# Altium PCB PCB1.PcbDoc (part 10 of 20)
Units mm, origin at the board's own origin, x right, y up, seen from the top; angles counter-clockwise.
Board outline 294.51 x 138.18 mm, 12 copper layers (Top Layer 1 _Signal, L2_GND, L3_Signals, L4_GND, L5_POWER, L6_Signals, L7_GND, L8_Signals, L9_GND, L10_POWER, L11_GND, Bottom Layer_Signals), stack 1.788 mm thick; 1254 components, 836 nets, 5699 pads, 2073 vias.
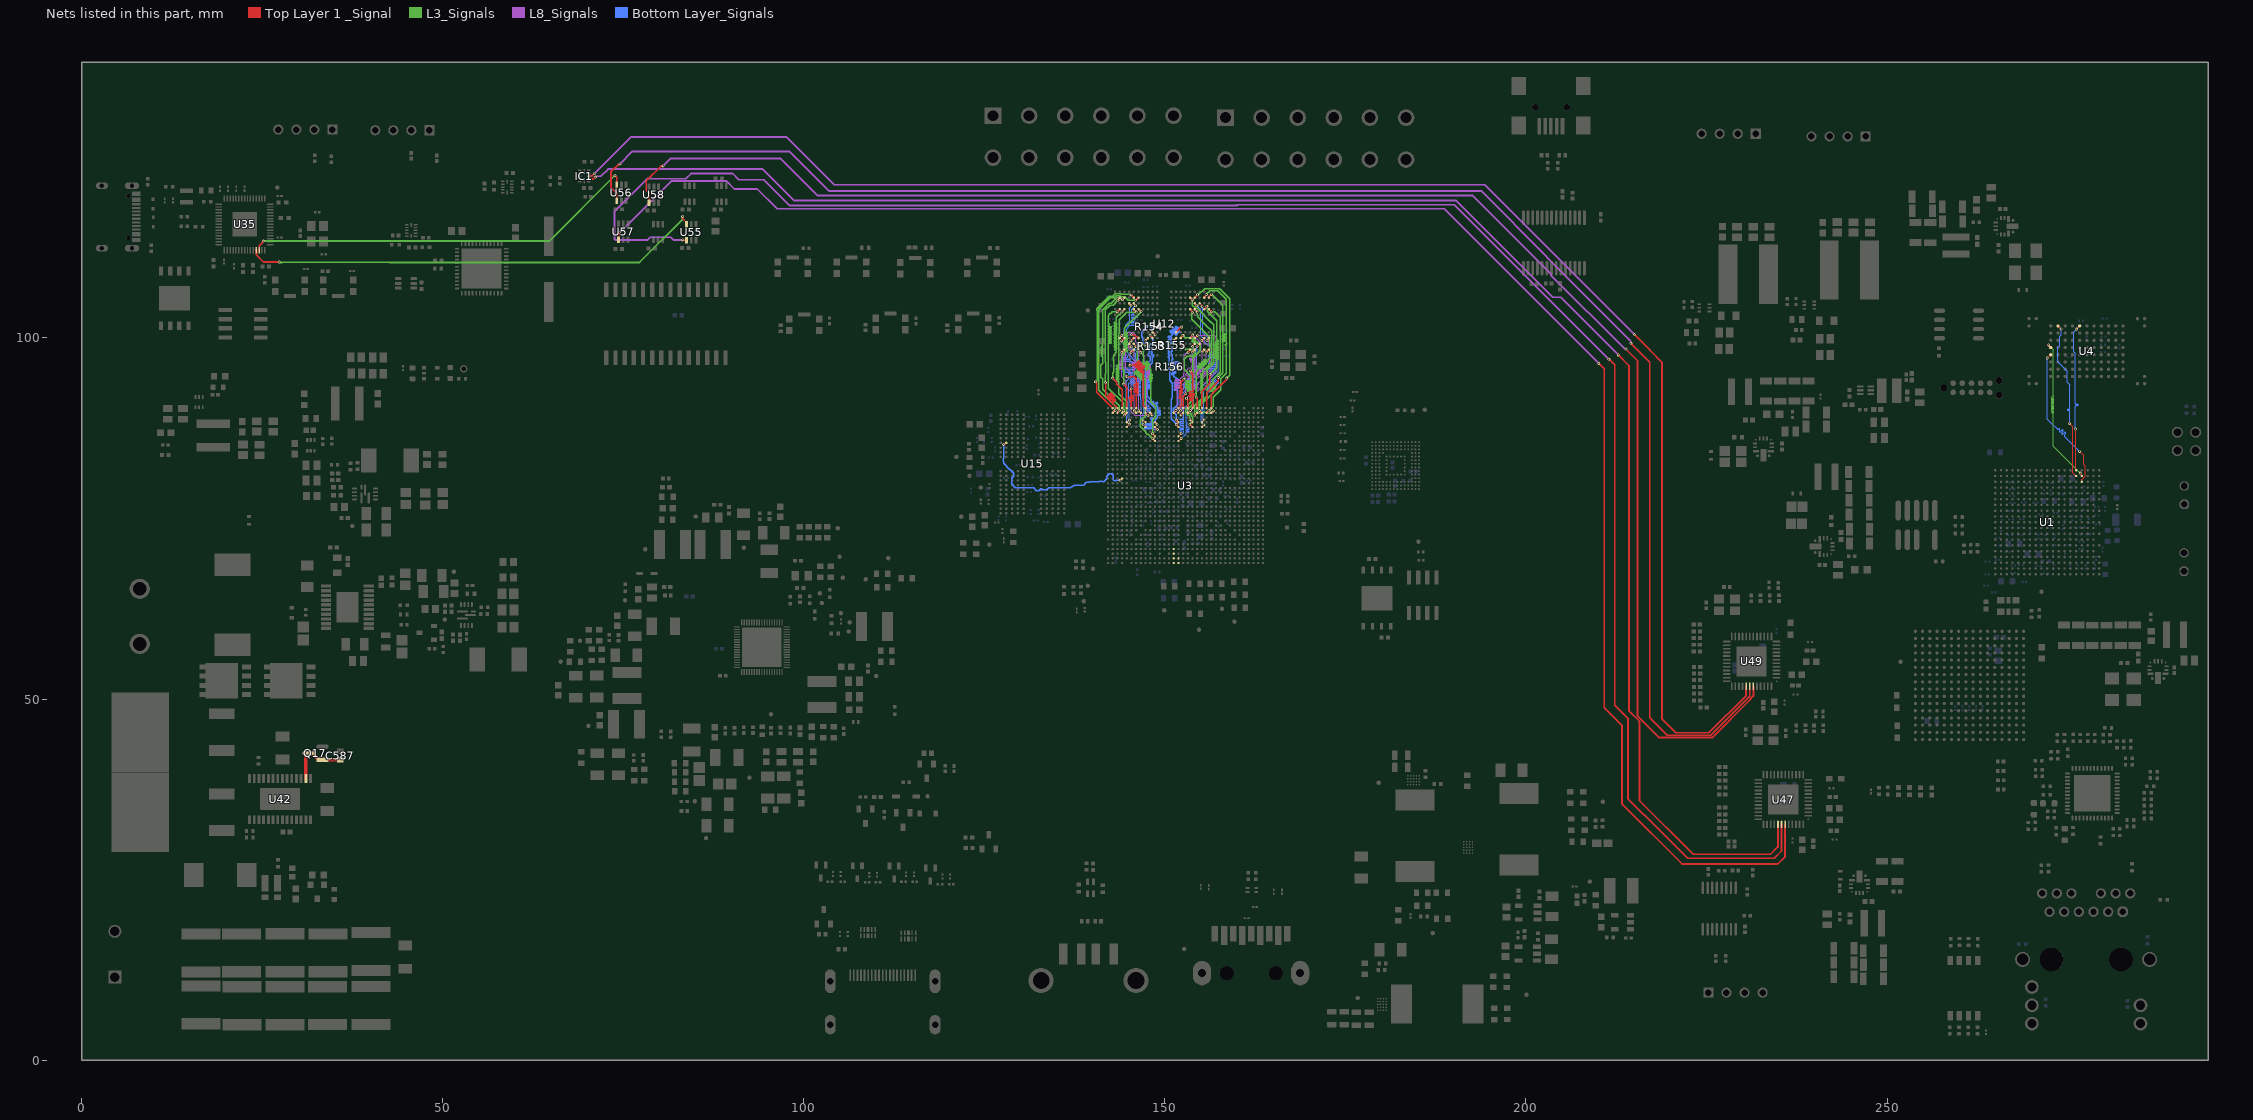
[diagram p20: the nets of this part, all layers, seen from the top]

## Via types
v1: diameter 0.4, hole 0.2, Top Layer 1 _Signal to Bottom Layer_Signals, 2009 vias
v2: diameter 0.508, hole 0.254, Top Layer 1 _Signal to Bottom Layer_Signals, 36 vias
v3: diameter 0.5, hole 0.2, Top Layer 1 _Signal to Bottom Layer_Signals, 12 vias
v4: diameter 1.27, hole 0.711, Top Layer 1 _Signal to Bottom Layer_Signals, 6 vias
v5: diameter 0.3, hole 0.2, Top Layer 1 _Signal to Bottom Layer_Signals, 5 vias
v6: diameter 0.254, hole 0.2, Top Layer 1 _Signal to Bottom Layer_Signals, 3 vias
v7: diameter 0.305, hole 0.2, Top Layer 1 _Signal to Bottom Layer_Signals, 1 vias
v8: diameter 0.254, hole 0.152, Top Layer 1 _Signal to Bottom Layer_Signals, 1 vias

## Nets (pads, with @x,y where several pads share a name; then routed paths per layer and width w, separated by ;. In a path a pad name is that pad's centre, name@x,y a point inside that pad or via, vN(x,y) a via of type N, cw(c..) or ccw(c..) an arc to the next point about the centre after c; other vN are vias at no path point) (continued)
DDR_CH1_DQ0_D: U3.A17 U12.AA2 | length 13.8
  Top Layer 1 _Signal w0.203: U3.A17@152.529,90.278 152.529,91.909 v1(152.889,92.269) ; v1@155.749,98.045 v1(155.758,98.045) 155.763,98.05 155.766,98.05 U12.AA2@156.104,98.389
  L8_Signals w0.135: v1(152.889,92.269) 152.889,93.591 153.838,94.539 153.885,94.587 153.838,94.634 153.951,94.747 154.197,94.502 154.311,94.615 154.065,94.861 154.178,94.974 154.424,94.728 154.537,94.842 154.291,95.087 154.405,95.201 154.651,94.955 154.764,95.068 154.518,95.314 154.631,95.427 154.877,95.182 154.991,95.295 154.745,95.541 154.858,95.654 155.104,95.408 155.217,95.522 154.971,95.767 155.085,95.881 155.331,95.635 155.444,95.748 155.245,95.947 155.372,96.074 155.758,96.46 v1(155.758,98.045)
DDR_CH1_DQ1_C: U3.B9 U12.C2 | length 15.5
  Top Layer 1 _Signal w0.203: v1(144.028,97.964) 144.028,97.988 144.404,98.365 U12.C2@144.404,98.389 ; U3.B9@147.329,89.628 147.329,89.602 147.651,89.28 v1(147.654,89.28) v1@147.639,89.265
  L8_Signals w0.135: v1(144.028,97.964) 144.028,97.3 144.028,97.155 143.96,97.155 143.96,96.995 144.081,96.995 144.081,96.835 143.708,96.835 143.708,96.674 144.081,96.674 144.081,96.514 143.708,96.514 143.708,96.354 144.081,96.354 144.081,96.194 143.708,96.194 143.708,96.033 144.081,96.033 144.081,95.873 143.708,95.873 143.708,95.713 144.028,95.713 144.028,95.645 144.028,94.631 144.642,94.017 144.642,93.176 145.338,92.48 145.338,89.791 145.849,89.28 v1(147.654,89.28)
DDR_CH1_DQ1_D: U3.B16 U12.Y2 | length 16.5
  Top Layer 1 _Signal w0.205: U3.B16@151.879,89.628 151.879,89.659 152.159,89.938 v1(152.165,89.938) ; v1(155.143,98.027) 155.143,98.038 155.454,98.35 U12.Y2@155.454,98.389
  L8_Signals w0.135: v1(152.165,89.938) 152.165,92.632 152.638,93.104 152.638,93.743 153.12,94.225 153.168,94.273 153.033,94.407 153.147,94.521 153.328,94.339 153.441,94.452 153.063,94.831 153.176,94.944 153.521,94.6 153.634,94.713 153.383,94.964 153.497,95.077 153.734,94.84 153.848,94.953 153.712,95.088 153.826,95.201 153.961,95.066 154.074,95.18 153.907,95.347 154.02,95.46 154.188,95.293 154.301,95.406 154.072,95.635 154.185,95.749 154.414,95.52 154.528,95.633 154.299,95.862 154.412,95.975 154.641,95.746 154.754,95.86 154.525,96.089 154.639,96.202 154.867,95.973 154.981,96.086 154.591,96.476 154.704,96.589 155.141,96.152 155.255,96.266 155.143,96.377 155.143,96.74 v1(155.143,98.027)
DDR_CH1_DQ2_C: U3.A9 U12.E2 | length 15.7
  Top Layer 1 _Signal w0.203: v1(145.177,96.215) 145.197,96.195 145.643,96.195 145.784,96.195 145.785,96.193 146.4,96.808 146.562,96.647 145.929,96.014 146.09,95.852 146.723,96.485 146.885,96.324 146.252,95.691 146.414,95.529 147.047,96.162 147.208,96 146.575,95.367 146.737,95.206 147.014,95.483 147.176,95.321 146.917,95.062 147.005,94.973 147.022,94.957 147.022,90.617 147.329,90.31 U3.A9@147.329,90.278 ; v1(145.338,97.968) 145.338,98.023 U12.E2@145.704,98.389
  L8_Signals w0.135: v1(145.177,96.215) 145.177,97.735 145.338,97.896 v1(145.338,97.968)
DDR_CH1_DQ2_D: U3.A16 U12.V2 | length 16
  Top Layer 1 _Signal w0.205: U3.A16@151.879,90.278 152.241,90.64 152.241,91.519 152.241,91.622 152.001,91.622 152.001,91.853 152.241,91.853 152.241,92.083 152.074,92.083 152.074,92.314 152.413,92.314 152.413,92.544 152.062,92.544 152.062,92.775 152.413,92.775 152.413,93.006 152.163,93.006 152.163,93.236 152.241,93.236 152.241,93.612 152.241,93.914 v1(152.629,94.302) ; v1(153.811,98.04) 153.811,98.046 U12.V2@154.154,98.389
  L8_Signals w0.135: v1(152.629,94.302) 152.844,94.517 152.844,94.928 153.071,95.154 153.071,95.627 153.298,95.853 153.671,95.853 153.706,95.888 153.774,95.956 153.774,96.09 153.74,96.09 153.74,96.251 154.069,96.251 154.069,96.411 153.768,96.411 153.768,96.571 154.154,96.571 154.154,96.732 153.607,96.732 153.607,96.892 154.154,96.892 154.154,97.052 153.428,97.052 153.428,97.212 154.154,97.212 154.154,97.373 153.428,97.373 153.428,97.533 153.811,97.533 153.811,97.651 v1(153.811,98.04)
DDR_CH1_DQ3_C: U3.B10 U12.F2 | length 16.5
  Top Layer 1 _Signal w0.203: U12.F2@146.354,98.389 146.354,98.349 146.658,98.045 v1(146.658,97.96) ; U3.B10@147.979,89.628 147.979,89.596 v1(148.237,89.339) v1@148.237,89.269
  L8_Signals w0.135: v1(146.658,97.96) 147.113,97.506 147.113,96.579 147.517,96.175 147.517,96.108 148.065,96.108 148.065,95.948 147.492,95.948 147.492,95.787 148.065,95.787 148.065,95.627 147.492,95.627 147.492,95.467 148.065,95.467 148.065,95.306 147.492,95.306 147.492,95.146 148.065,95.146 148.065,94.986 147.492,94.986 147.492,94.826 148.065,94.826 148.065,94.665 147.492,94.665 147.492,94.505 147.765,94.505 147.765,94.345 147.517,94.345 147.517,92.97 147.517,90.059 v1(148.237,89.339)
DDR_CH1_DQ3_D: U3.B15 U12.U2 | length 16.6
  Top Layer 1 _Signal w0.205: U3.B15@151.229,89.628 151.229,89.639 151.53,89.94 v1(151.53,89.952) ; v1(153.209,97.997) 153.246,98.035 153.246,98.092 153.504,98.35 U12.U2@153.504,98.389
  L8_Signals w0.135: v1(151.53,89.952) 151.53,90.026 151.681,90.177 151.681,92.062 151.749,92.13 151.749,92.421 151.681,92.489 151.681,92.772 151.681,92.84 151.43,92.84 151.43,93 152.178,93 152.178,93.16 151.43,93.16 151.43,93.321 152.178,93.321 152.178,93.481 151.43,93.481 151.43,93.641 152.178,93.641 152.178,93.801 151.43,93.801 151.43,93.962 152.178,93.962 152.178,94.122 151.43,94.122 151.43,94.282 152.111,94.282 152.226,94.397 152.625,94.797 152.625,95.018 152.708,95.101 152.708,96.375 152.701,96.382 152.701,96.748 152.681,96.767 152.681,97.058 152.701,97.078 152.701,97.657 152.907,97.862 153.002,97.862 153.137,97.997 v1(153.209,97.997)
DDR_CH1_DQ4_C: U3.A6 U12.F4 | length 14.2
  Top Layer 1 _Signal w0.203: v1(145.352,92.964) 145.366,92.95 145.366,92.108 145.366,92.007 145.622,92.007 145.622,91.778 145.062,91.778 145.062,91.549 145.622,91.549 145.622,91.321 145.238,91.321 145.238,91.092 145.366,91.092 145.366,90.619 145.366,90.292 U3.A6@145.379,90.278 ; v1(145.393,100.452) 145.431,100.414 145.713,100.414 145.778,100.349 145.854,100.349 146.062,100.141 146.162,100.141 146.315,99.989 U12.F4@146.354,99.989
  L8_Signals w0.135: v1(145.352,92.964) 145.357,92.969 145.357,95.095 144.593,95.859 144.593,97.724 144.598,97.728 144.598,98.2 144.593,98.205 144.593,100.12 144.934,100.461 145.384,100.461 v1(145.393,100.452)
DDR_CH1_DQ4_D: U3.A19 U12.U4 | length 15.5
  Top Layer 1 _Signal w0.203: U12.U4@153.504,99.989 153.863,100.347 v1(153.863,100.401) ; v1(153.556,95.428) 153.556,95.375 153.881,95.05 153.881,93.532 153.881,92.742 153.948,92.742 153.948,92.513 153.348,92.513 153.348,92.285 154.063,92.285 154.063,92.056 153.348,92.056 153.348,91.827 153.959,91.827 153.959,91.599 153.467,91.599 153.467,91.37 153.8,91.37 153.8,91.269 153.8,91.228 153.829,91.199 U3.A19@153.829,90.278
  L8_Signals w0.135: v1(153.556,95.428) 154.372,96.245 154.372,97.754 155.041,98.423 155.041,99.174 154.754,99.461 154.754,99.51 v1(153.863,100.401)
DDR_CH1_DQ5_C: U3.B7 U12.E4 | length 15
  Top Layer 1 _Signal w0.205: v1(145.297,99.599) 145.306,99.599 145.695,99.989 U12.E4@145.704,99.989 ; v1(145.768,89.859) 145.998,89.628 U3.B7@146.029,89.628
  L8_Signals w0.135: v1(145.297,99.599) 144.977,99.28 144.977,98.631 145.275,98.333 145.47,98.333 145.768,98.035 145.768,97.822 145.768,97.037 ; 145.767,97.037 145.767,96.876 145.994,96.876 145.994,96.716 145.526,96.716 145.526,96.556 145.994,96.556 145.994,96.396 145.528,96.396 145.528,96.235 145.994,96.235 145.994,96.075 145.526,96.075 145.526,95.915 145.994,95.915 145.994,95.755 145.526,95.755 145.526,95.594 145.768,95.594 145.768,95.527 v1(145.768,89.859)
DDR_CH1_DQ5_D: U3.B18 U12.V4 | length 15.3
  Top Layer 1 _Signal w0.203: U3.B18@153.179,89.628 153.211,89.628 153.527,89.944 v1(153.527,89.953) ; U12.V4@154.154,99.989 154.506,100.34 154.514,100.34 v1(154.531,100.358)
  L8_Signals w0.135: v1(153.527,89.953) 153.527,90.025 153.64,90.138 ; 153.64,90.139 153.984,90.482 153.984,92.155 156.595,94.766 156.595,94.806 157.124,95.336 157.124,100.072 156.838,100.358 v1(154.531,100.358)
DDR_CH1_DQ6_C: U3.A7 U12.C4 | length 15
  Top Layer 1 _Signal w0.203: v1(143.979,99.589) 144.023,99.633 144.048,99.633 U12.C4@144.404,99.989 ; v1(144.764,94.628) 145.783,94.628 146.029,94.382 146.029,93.917 146.029,93.816 146.266,93.816 146.266,93.587 145.77,93.587 145.77,93.359 146.266,93.359 146.266,93.13 145.77,93.13 145.77,92.901 146.266,92.901 146.266,92.673 145.77,92.673 145.77,92.444 146.266,92.444 146.266,92.216 145.945,92.216 145.945,91.987 146.029,91.987 146.029,91.761 U3.A7@146.029,90.278
  L8_Signals w0.135: v1(143.979,99.589) 144.374,99.194 144.374,98.115 144.379,98.11 144.379,97.819 144.374,97.814 144.374,95.018 v1(144.764,94.628)
DDR_CH1_DQ6_D: U3.A18 U12.Y4 | length 14.8
  Top Layer 1 _Signal w0.205: v1(152.993,91.648) 152.993,91.596 153.179,91.409 U3.A18@153.179,90.278 ; v1(155.105,99.633) 155.105,99.636 155.454,99.985 U12.Y4@155.454,99.989
  L8_Signals w0.135: v1(152.993,91.648) 152.993,91.653 153.465,92.125 153.465,93.353 154.722,94.611 154.77,94.658 154.752,94.676 154.865,94.79 155.097,94.558 155.21,94.672 154.979,94.903 155.092,95.016 155.323,94.785 155.437,94.898 155.205,95.13 155.319,95.243 155.55,95.012 155.663,95.125 155.432,95.356 155.545,95.47 155.77,95.245 155.884,95.358 155.659,95.583 155.772,95.696 155.862,95.606 155.975,95.72 155.903,95.792 156.034,95.922 156.226,96.114 156.226,98.827 155.831,99.222 155.603,99.222 155.384,99.441 155.368,99.441 155.177,99.633 v1(155.105,99.633)
DDR_CH1_DQ7_C: U3.B8 U12.B4 | length 15.4
  Top Layer 1 _Signal w0.203: U12.B4@143.754,99.989 143.754,100.028 144.035,100.309 v1(144.035,100.348) ; v1@146.368,89.899 v1(146.381,89.899) 146.381,89.895 146.648,89.628 U3.B8@146.679,89.628
  L8_Signals w0.135: v1(144.035,100.348) 144.489,100.803 145.539,100.803 145.953,100.388 145.953,99.446 146.368,99.032 146.368,98.167 146.307,98.106 146.307,96.518 146.307,96.45 146.563,96.45 146.563,96.29 146.282,96.29 146.282,96.13 146.563,96.13 146.563,95.969 146.282,95.969 146.282,95.809 146.51,95.809 146.51,95.649 146.307,95.649 146.307,94.309 146.381,94.235 146.381,94.025 v1(146.381,89.899)
DDR_CH1_DQ7_D: U3.B17 U12.AA4 | length 16.2
  Top Layer 1 _Signal w0.203: v1(152.254,89.344) 152.254,89.348 152.529,89.624 U3.B17@152.529,89.628 ; v1(155.837,99.648) 155.837,99.682 156.104,99.949 U12.AA4@156.104,99.989
  L8_Signals w0.135: v1(152.254,89.344) 152.305,89.395 152.305,89.581 152.516,89.793 152.516,90.14 153.698,91.322 153.698,92.85 153.804,92.956 153.852,93.004 153.75,93.105 153.864,93.219 154.301,92.781 154.414,92.895 153.977,93.332 154.09,93.445 154.527,93.008 154.641,93.121 154.203,93.559 154.317,93.672 154.508,93.48 154.622,93.594 154.532,93.684 155.892,95.044 155.892,95.057 155.946,95.111 156.098,95.263 156.111,95.263 156.448,95.601 156.448,99.036 v1(155.837,99.648)
DDR_CH1_DQ8_C: U3.A3 U12.B11 | length 22
  Top Layer 1 _Signal w0.205: v1(141.768,93.82) 141.793,93.796 141.793,92.103 141.793,91.958 141.938,91.813 142.544,92.419 142.707,92.256 142.061,91.61 142.224,91.447 142.87,92.093 143.033,91.93 142.387,91.284 142.551,91.121 143.021,91.591 143.184,91.428 142.732,90.976 143.176,90.531 U3.A3@143.429,90.278 ; v1(143.504,105.223) 143.541,105.26 143.541,105.337 143.754,105.55 U12.B11@143.754,105.589
  L3_Signals w0.179: v1(141.768,93.82) 141.768,95.018 141.781,95.03 141.781,96.628 141.768,96.64 141.768,98.62 141.768,101.629 141.768,103.9 142.42,104.552 142.833,104.552 v1(143.504,105.223)
DDR_CH1_DQ8_D: U3.A22 U12.AA11 | length 19.8
  Top Layer 1 _Signal w0.203: U3.A22@155.779,90.278 155.779,92.388 157.407,94.015 157.407,94.506 v1(157.42,94.52) ; U12.AA11@156.104,105.589 156.104,105.629 156.172,105.696 156.172,105.741 v1(156.461,106.03)
  L3_Signals w0.179: v1(156.461,106.03) 157.994,104.497 157.994,100.686 157.994,100.596 158.259,100.596 158.259,100.392 157.917,100.392 157.917,100.187 158.259,100.187 158.259,99.982 157.917,99.982 157.917,99.778 158.259,99.778 158.259,99.573 157.974,99.573 157.974,99.368 157.994,99.368 157.994,98.27 157.994,95.153 157.42,94.58 v1(157.42,94.52)
DDR_CH1_DQ9_C: U3.B3 U12.C11 | length 21.8
  Top Layer 1 _Signal w0.203: v1(144.154,105.28) 144.154,105.309 144.404,105.56 U12.C11@144.404,105.589
  Top Layer 1 _Signal w0.205: U3.B3@143.429,89.628 143.429,89.641 143.706,89.918 v1(143.706,89.93)
  L3_Signals w0.179: v1(143.706,89.93) 143.706,90.579 141.395,92.89 141.395,94.328 141.138,94.585 141.138,96.231 141.395,96.488 141.395,97.348 141.395,97.437 141.162,97.437 141.162,97.642 141.42,97.642 141.42,97.847 141.162,97.847 141.162,98.051 141.42,98.051 141.42,98.256 141.162,98.256 141.162,98.461 141.42,98.461 141.42,98.666 141.162,98.666 141.162,98.87 141.42,98.87 141.42,99.075 141.322,99.075 141.322,99.28 141.395,99.28 141.395,101.306 141.395,103.899 142.311,104.815 142.568,104.815 143.349,105.596 143.659,105.596 143.819,105.437 143.938,105.437 144.094,105.28 v1(144.154,105.28)
DDR_CH1_DQ9_D: U3.B22 U12.Y11 | length 21.3
  Top Layer 1 _Signal w0.203: U12.Y11@155.454,105.589 155.454,105.629 155.761,105.935 v1(155.761,106.016) ; U3.B22@155.779,89.628 v1(156.097,89.945)
  L3_Signals w0.179: v1(155.761,106.016) 156.308,106.564 157.346,106.564 158.522,105.388 158.522,99.424 158.522,99.335 158.547,99.335 158.547,99.13 158.365,99.13 158.365,98.925 158.522,98.925 158.522,96.478 158.522,95.093 157.744,94.316 157.744,92.816 156.709,91.78 156.709,90.557 v1(156.097,89.945)
DDR_CH1_DQ10_C: U3.A2 U12.E11 | length 21.1
  Top Layer 1 _Signal w0.205: v1(140.405,93.926) 140.405,93.873 140.552,93.727 140.552,92.506 U3.A2@142.779,90.278 ; v1(145.325,105.96) 145.329,105.96 145.7,105.589 U12.E11@145.704,105.589
  L3_Signals w0.179: v1(140.405,93.926) 140.405,93.935 140.612,94.141 140.612,103.782 140.58,103.814 140.58,104.068 142.315,105.803 142.812,105.803 143.131,106.123 143.877,106.123 143.98,106.019 145.109,106.019 145.127,106.002 145.282,106.002 v1(145.325,105.96)
DDR_CH1_DQ10_D: U3.A23 U12.V11 | length 22.1
  Top Layer 1 _Signal w0.203: U12.V11@154.154,105.589 154.521,105.955 v1(154.521,105.975) ; U3.A23@156.429,90.278 156.429,92.164 158.537,94.272 158.537,94.405 v1(158.575,94.443)
  L3_Signals w0.179: v1(154.521,105.975) 154.563,106.017 154.702,106.017 155.517,106.832 157.567,106.832 158.987,105.413 158.987,94.855 v1(158.575,94.443)
DDR_CH1_DQ11_C: U3.B2 U12.F11 | length 22.1
  Top Layer 1 _Signal w0.203: U3.B2@142.779,89.628 142.779,89.66 143.091,89.971 v1(143.1,89.971) v1@143.101,89.969 ; v1(145.973,105.217) 145.978,105.217 146.35,105.589 U12.F11@146.354,105.589
  L3_Signals w0.179: v1(143.1,89.971) 143.1,90.534 140.875,92.759 140.875,103.991 142.424,105.54 142.921,105.54 143.24,105.86 143.768,105.86 143.928,105.7 144.47,105.7 144.952,105.217 v1(145.973,105.217)
DDR_CH1_DQ11_D: U3.B23 U12.U11 | length 21.3
  Top Layer 1 _Signal w0.205: U12.U11@153.504,105.589 153.504,105.583 153.805,105.282 v1(153.805,105.276) ; U3.B23@156.429,89.628 156.46,89.628 156.725,89.892 v1(156.725,89.895)
  L3_Signals w0.179: v1(153.805,105.276) 153.805,104.559 154.286,104.078 154.484,104.078 155.435,103.127 155.435,103.089 156.386,102.138 156.421,102.138 156.759,101.8 156.759,99.401 156.737,99.379 156.737,96.501 155.87,95.634 155.87,92.009 154.419,90.558 154.419,89.73 154.573,89.575 155.097,89.575 155.242,89.72 155.702,89.72 155.85,89.571 156.385,89.571 156.709,89.895 v1(156.725,89.895)
DDR_CH1_DQ12_C: U3.A5 U12.F9 | length 21.8
  Top Layer 1 _Signal w0.203: v1(144.291,93.598) 144.729,93.16 U3.A5@144.729,90.278 ; U12.F9@146.354,103.989 v1(146.701,103.642)
  L3_Signals w0.179: v1(144.291,93.598) 144.291,95.512 144.1,95.703 144.1,97.508 144.402,97.81 144.435,97.844 144.435,97.9 144.401,97.9 144.401,98.105 144.816,98.105 144.816,98.31 144.233,98.31 144.233,98.514 144.816,98.514 144.816,98.719 144.353,98.719 144.353,98.924 144.816,98.924 144.816,99.128 144.252,99.128 144.252,99.333 144.816,99.333 144.816,99.538 144.353,99.538 144.353,99.743 144.816,99.743 144.816,99.947 144.367,99.947 144.367,100.152 144.816,100.152 144.816,100.357 144.408,100.357 144.408,100.561 144.779,100.561 144.779,100.766 144.435,100.766 144.435,100.975 144.435,101.377 v1(146.701,103.642)
DDR_CH1_DQ12_D: U3.A20 U12.U9 | length 20.3
  Top Layer 1 _Signal w0.203: U12.U9@153.504,103.989 153.504,103.949 153.782,103.672 153.782,103.573 v1(153.819,103.535) ; v1(154.345,91.792) 154.345,91.739 154.479,91.604 U3.A20@154.479,90.278
  L3_Signals w0.179: v1(153.819,103.535) 153.819,103.475 153.708,103.363 153.708,102.617 156.211,100.114 156.211,97.22 156.076,97.086 155.92,96.929 156.03,96.819 155.886,96.674 155.514,97.046 155.369,96.901 155.78,96.49 155.635,96.345 155.224,96.756 155.079,96.612 155.491,96.2 155.346,96.055 154.935,96.467 154.79,96.322 155.201,95.911 155.056,95.766 154.645,96.177 154.5,96.033 154.762,95.771 154.698,95.708 154.335,95.344 154.335,91.802 v1(154.345,91.792)
DDR_CH1_DQ13_C: U3.B5 U12.E9 | length 22
  Top Layer 1 _Signal w0.203: v1(144.418,89.316) U3.B5@144.729,89.628 ; U12.E9@145.704,103.989 145.704,103.949 146.032,103.621 v1(146.032,103.582)
  L3_Signals w0.179: 143.606,93.671 143.606,92.291 144.576,91.321 144.576,91.233 144.686,91.123 144.686,89.644 144.418,89.376 v1(144.418,89.316) ; 143.606,93.982 143.606,93.987 143.246,93.987 143.246,94.192 143.631,94.192 143.631,94.397 143.246,94.397 143.246,94.601 143.631,94.601 143.631,94.806 143.246,94.806 143.246,95.011 143.631,95.011 143.631,95.216 143.246,95.216 143.246,95.42 143.631,95.42 143.631,95.625 143.246,95.625 143.246,95.83 143.631,95.83 143.631,96.035 143.306,96.035 143.306,96.239 143.606,96.239 143.606,96.8 143.606,100.447 143.709,100.55 143.709,102.551 144.74,103.582 v1(146.032,103.582) ; 143.607,93.672 143.607,93.898 143.607,93.982
DDR_CH1_DQ13_D: U3.B20 U12.V9 | length 20.9
  Top Layer 1 _Signal w0.203: v1(154.145,89.301) 154.149,89.301 154.476,89.628 U3.B20@154.479,89.628 ; U12.V9@154.154,103.989 154.154,103.949 154.418,103.686 154.418,103.616 v1(154.455,103.578)
  L3_Signals w0.179: v1(154.145,89.301) 154.145,90.656 155.24,91.751 155.24,92.258 155.24,92.348 154.991,92.348 154.991,92.553 155.265,92.553 155.265,92.757 154.991,92.757 154.991,92.962 155.265,92.962 155.265,93.167 154.991,93.167 154.991,93.371 155.265,93.371 155.265,93.576 154.991,93.576 154.991,93.781 155.265,93.781 155.265,93.986 154.991,93.986 154.991,94.19 155.265,94.19 155.265,94.395 154.991,94.395 154.991,94.6 155.265,94.6 155.265,94.805 154.991,94.805 154.991,95.009 155.24,95.009 155.24,95.282 155.24,95.376 156.474,96.61 156.474,100.782 156.496,100.804 156.496,100.977 155.822,101.65 155.818,101.65 154.524,102.944 154.524,102.99 154.455,103.059 v1(154.455,103.578)
DDR_CH1_DQ14_C: U3.A4 U12.C9 | length 21.7
  Top Layer 1 _Signal w0.203: v1(142.755,94.446) 143.324,93.876 143.324,93.611 144.079,92.856 U3.A4@144.079,90.278 ; v1(144.038,103.589) 144.038,103.606 144.404,103.972 U12.C9@144.404,103.989
  L3_Signals w0.179: v1(142.755,94.446) 142.755,95.121 142.935,95.302 142.935,95.821 142.926,95.83 142.926,96.926 142.859,96.994 142.859,97.303 142.926,97.371 142.926,97.618 143.292,97.983 143.292,98.186 143.292,98.275 143.082,98.275 143.082,98.48 143.317,98.48 143.317,98.685 142.961,98.685 142.961,98.89 143.317,98.89 143.317,99.094 142.961,99.094 142.961,99.299 143.317,99.299 143.317,99.504 142.961,99.504 142.961,99.709 143.317,99.709 143.317,99.913 142.961,99.913 142.961,100.118 143.317,100.118 143.317,100.323 142.961,100.323 142.961,100.527 143.317,100.527 143.317,100.732 142.961,100.732 142.961,100.937 143.317,100.937 143.317,101.142 142.961,101.142 142.961,101.346 143.317,101.346 143.317,101.551 142.961,101.551 142.961,101.756 143.317,101.756 143.317,101.96 143.009,101.96 143.009,102.165 143.292,102.165 143.292,102.304 143.292,102.843 v1(144.038,103.589)
DDR_CH1_DQ14_D: U3.A21 U12.Y9 | length 21.3
  Top Layer 1 _Signal w0.203: U3.A21@155.129,90.278 155.129,92.578 156.243,93.692 v1(156.243,94.912) ; U12.Y9@155.454,103.989 155.809,104.344 v1(155.809,104.388)
  L3_Signals w0.179: v1(155.809,104.388) 155.852,104.345 155.852,104.209 155.888,104.172 155.888,103.664 156.537,103.015 156.565,103.015 157.214,102.367 157.214,99.746 157.214,99.656 157.391,99.656 157.391,99.452 157.022,99.452 157.022,99.247 157.391,99.247 157.391,99.042 157,99.042 157,98.837 157.391,98.837 157.391,98.633 157,98.633 157,98.428 157.391,98.428 157.391,98.223 157,98.223 157,98.019 157.391,98.019 157.391,97.814 157,97.814 157,97.609 157.391,97.609 157.391,97.404 157,97.404 157,97.2 157.391,97.2 157.391,96.995 157.118,96.995 157.118,96.79 157.214,96.79 157.214,95.882 157.202,95.87 v1(156.243,94.912)
DDR_CH1_DQ15_C: U3.B4 U12.B9 | length 21.5
  Top Layer 1 _Signal w0.205: v1(143.411,103.603) 143.411,103.624 143.754,103.968 U12.B9@143.754,103.989 ; U3.B4@144.079,89.628 144.079,89.659 144.312,89.892 v1(144.312,89.9)
  L3_Signals w0.179: v1(143.411,103.603) 142.746,103.603 142.579,103.437 142.44,103.437 142.221,103.218 142.221,103.079 142.181,103.039 142.181,102.498 142.181,101.932 142.265,101.932 142.265,101.728 142.156,101.728 142.156,101.523 142.56,101.523 142.56,101.318 142.156,101.318 142.156,101.114 142.56,101.114 142.56,100.909 142.156,100.909 142.156,100.704 142.56,100.704 142.56,100.499 142.156,100.499 142.156,100.295 142.56,100.295 142.56,100.09 142.156,100.09 142.156,99.885 142.56,99.885 142.56,99.681 142.156,99.681 142.156,99.476 142.56,99.476 142.56,99.271 142.156,99.271 142.156,99.066 142.181,99.066 142.181,98.977 142.181,93.064 144.312,90.933 v1(144.312,89.9)
DDR_CH1_DQ15_D: U3.B21 U12.AA9 | length 21.1
  Top Layer 1 _Signal w0.205: v1(154.792,89.949) 154.8,89.949 155.113,89.636 155.113,89.628 U3.B21@155.129,89.628 ; U12.AA9@156.104,103.989 156.104,103.982 156.466,103.621 v1(156.466,103.614)
  L3_Signals w0.179: v1(154.792,89.949) 154.792,90.511 156.61,92.329 156.61,92.379 156.61,92.469 156.61,92.648 156.196,92.648 156.196,92.853 157.033,92.853 157.033,93.058 156.196,93.058 156.196,93.262 157.033,93.262 157.033,93.467 156.196,93.467 156.196,93.672 156.794,93.672 156.794,93.877 156.612,93.877 156.612,94.054 156.612,94.151 156.613,94.24 157.654,95.282 157.654,102.872 156.912,103.614 v1(156.466,103.614)
DDR_CH1_DQS0_C_N: U3.D9 U12.E3 | length 20.1
  Top Layer 1 _Signal w0.161: U12.E3@145.704,99.189 146.017,98.876 v1(146.017,98.781) ; v1(146.999,88.483) 147.011,88.471 147.143,88.471 147.286,88.328 U3.D9@147.329,88.328
  Bottom Layer_Signals w0.161: v1(146.017,98.781) 146.017,98.752 145.832,98.567 145.832,98.433 146.294,97.971 146.294,97.155 146.318,97.131 146.318,97.054 146.414,96.958 146.414,96.659 146.858,96.659 146.858,96.472 146.414,96.472 146.414,96.285 147.048,96.285 147.048,96.099 146.519,96.099 146.519,95.912 146.6,95.831 146.622,95.809 146.712,95.809 147.001,95.519 147.001,91.549 147.059,91.491 147.059,91.181 147.059,91.1 147.449,91.1 147.449,90.914 147.059,90.914 147.059,90.727 147.823,90.727 147.823,90.54 147.059,90.54 147.059,90.354 148.072,90.354 148.072,90.167 147.059,90.167 147.059,89.98 147.977,89.98 147.977,89.794 147.059,89.794 147.059,89.607 147.048,89.607 146.999,89.558 146.999,89.358 v1(146.999,88.483)
DDR_CH1_DQS0_C_P: U3.E9 U12.D3 | length 20.3
  Top Layer 1 _Signal w0.161: U12.D3@145.054,99.189 145.054,99.148 145.329,98.874 v1(145.329,98.777) ; v1@146.981,87.992 v1(146.993,87.992) 147.002,87.982 147.025,87.982 U3.E9@147.329,87.678
  Bottom Layer_Signals w0.161: v1(145.329,98.777) 145.329,98.75 145.518,98.561 145.518,98.303 145.98,97.841 145.98,97.025 146.004,97.001 146.004,96.924 146.1,96.828 146.1,95.887 146.492,95.495 146.582,95.495 146.688,95.39 146.688,95.16 146.688,94.833 146.211,94.833 146.211,94.646 146.688,94.646 146.688,94.459 146.211,94.459 146.211,94.273 146.688,94.273 146.688,94.086 146.211,94.086 146.211,93.899 146.688,93.899 146.688,93.713 146.211,93.713 146.211,93.526 146.688,93.526 146.688,93.339 146.211,93.339 146.211,93.153 146.688,93.153 146.688,92.966 146.211,92.966 146.211,92.779 146.688,92.779 146.688,92.593 146.211,92.593 146.211,92.406 146.688,92.406 146.688,92.219 146.211,92.219 146.211,92.033 146.688,92.033 146.688,91.952 146.688,91.419 146.745,91.361 146.745,89.748 146.685,89.688 146.685,89.358 146.669,89.342 146.669,88.668 146.635,88.634 146.635,88.332 146.975,87.992 v1(146.993,87.992)
DDR_CH1_DQS0_D_N: U3.G16 U12.V3 | length 23.3
  Top Layer 1 _Signal w0.161: U3.G16@151.879,86.378 152.239,86.738 v1(152.239,86.741) ; v1(153.831,98.798) 153.831,98.866 U12.V3@154.154,99.189
  Bottom Layer_Signals w0.161: v1(152.239,86.741) 152.257,86.758 152.524,86.758 152.618,86.853 152.618,87.068 152.618,87.149 152.122,87.149 152.122,87.335 152.618,87.335 152.618,87.522 152.122,87.522 152.122,87.709 152.618,87.709 152.618,87.895 152.122,87.895 152.122,88.082 152.618,88.082 152.618,88.269 152.122,88.269 152.122,88.455 152.618,88.455 152.618,88.642 152.122,88.642 152.122,88.829 152.618,88.829 152.618,89.499 152.618,90 152.211,90.408 152.211,92.55 152.784,93.123 152.841,93.18 152.502,93.518 152.634,93.65 152.973,93.312 153.105,93.444 152.766,93.782 152.898,93.914 153.237,93.576 153.369,93.708 153.03,94.046 153.162,94.179 153.501,93.84 153.633,93.972 153.294,94.311 153.426,94.443 153.765,94.104 153.928,94.268 154.081,94.42 154.081,97.739 154.176,97.834 154.176,98.191 154.008,98.358 154.008,98.559 153.831,98.736 v1(153.831,98.798)
DDR_CH1_DQS0_D_P: U3.H16 U12.W3 | length 23.6
  Top Layer 1 _Signal w0.161: U3.H16@151.879,85.728 151.904,85.728 151.904,85.74 152.249,86.086 v1(152.262,86.086) ; v1(154.448,98.836) 154.45,98.836 154.801,99.187 154.801,99.189 U12.W3@154.804,99.189
  Bottom Layer_Signals w0.161: v1(152.262,86.086) 152.295,86.086 152.765,86.556 152.932,86.723 152.932,86.985 153.402,86.985 153.402,87.171 152.932,87.171 152.932,87.358 153.402,87.358 153.402,87.545 152.932,87.545 152.932,87.731 153.08,87.731 153.08,87.918 152.932,87.918 152.932,88.105 153.08,88.105 153.08,88.291 152.932,88.291 152.932,88.706 152.932,90.13 152.524,90.538 152.524,92.42 152.849,92.745 152.906,92.802 153.038,92.934 153.493,92.478 153.625,92.61 153.17,93.066 153.302,93.198 153.757,92.742 153.889,92.874 153.434,93.33 153.566,93.462 154.021,93.006 154.154,93.138 153.698,93.594 153.83,93.726 154.286,93.27 154.418,93.402 153.962,93.858 154.094,93.99 154.37,93.714 154.502,93.846 154.226,94.122 154.358,94.254 154.395,94.29 154.395,94.433 154.395,97.609 154.489,97.704 154.489,98.321 154.322,98.488 154.322,98.645 154.448,98.771 v1(154.448,98.836)
DDR_CH1_DQS1_C_N: U3.D5 U12.E10 | length 28
  Top Layer 1 _Signal w0.161: U3.D5@144.729,88.328 144.751,88.328 145.024,88.601 v1(145.114,88.601) ; U12.E10@145.704,104.789 145.704,104.738 145.913,104.529 v1(145.913,104.456)
  Bottom Layer_Signals w0.161: v1(145.114,88.601) 145.068,88.647 145.068,88.802 145.055,88.815 145.055,88.966 145.096,89.007 145.096,91.393 144.987,91.502 144.987,93.622 144.987,93.736 145.119,93.868 145.826,93.161 145.958,93.293 145.173,94.078 145.305,94.21 145.849,93.666 145.981,93.798 145.437,94.342 145.569,94.474 145.834,94.209 145.966,94.341 145.701,94.606 145.833,94.738 145.855,94.76 145.855,94.97 145.855,96.726 145.759,96.822 145.759,96.9 145.518,97.141 145.518,97.273 144.706,98.085 144.706,99.25 144.713,99.258 144.713,100.629 144.692,100.651 144.692,101.217 144.932,101.458 144.932,101.51 144.932,101.59 144.996,101.59 144.996,101.777 145.965,101.777 145.965,101.964 145.368,101.964 145.368,102.15 145.923,102.15 145.923,102.337 145.442,102.337 145.442,102.524 145.923,102.524 145.923,102.71 145.442,102.71 145.442,102.897 146.241,102.897 146.241,103.084 145.442,103.084 145.442,103.27 145.668,103.27 145.668,103.457 145.442,103.457 145.442,103.644 145.438,103.644 145.438,103.752 145.438,103.981 v1(145.913,104.456)
DDR_CH1_DQS1_C_P: U3.E5 U12.D10 | length 28.8
  Top Layer 1 _Signal w0.161: U3.E5@144.729,87.678 145.071,88.019 145.071,88.048 v1(145.086,88.063) ; U12.D10@145.054,104.789 145.054,104.738 v1(145.322,104.47)
  Bottom Layer_Signals w0.161: v1(145.086,88.063) 144.741,88.408 144.741,89.096 144.782,89.137 144.782,91.263 144.674,91.372 144.674,94.022 145.474,94.822 145.542,94.89 145.542,94.903 145.005,94.903 145.005,95.09 145.542,95.09 145.542,95.276 144.217,95.276 144.217,95.463 145.542,95.463 145.542,95.65 144.217,95.65 144.217,95.836 145.542,95.836 145.542,96.396 145.511,96.396 145.511,96.583 145.445,96.583 145.445,96.77 144.217,96.77 144.217,96.957 145.204,96.957 145.204,97.143 144.217,97.143 144.217,97.33 144.83,97.33 144.83,97.517 144.675,97.672 144.392,97.955 144.392,99.38 144.399,99.388 144.399,100.499 144.378,100.521 144.378,101.347 144.586,101.555 144.586,101.811 145.128,102.352 145.128,103.563 145.124,103.567 145.124,104.207 145.322,104.405 v1(145.322,104.47)
DDR_CH1_DQS1_D_N: U3.E21 U12.V10 | length 29
  Top Layer 1 _Signal w0.161: U12.V10@154.154,104.789 154.154,104.738 v1(154.441,104.451) ; U3.E21@155.129,87.678 155.399,87.947 v1(155.399,87.961)
  Bottom Layer_Signals w0.161: v1(154.441,104.451) 154.961,103.931 154.961,100.31 155.473,99.799 155.473,99.497 155.686,99.283 155.725,99.283 156.2,98.808 156.2,98.04 156.2,97.99 156.233,97.958 156.365,97.826 156.021,97.482 156.153,97.35 156.497,97.694 156.629,97.562 156.285,97.218 156.417,97.086 156.761,97.43 156.913,97.278 156.97,97.221 157.085,97.106 157.085,96.85 157.085,96.554 156.056,96.554 156.056,96.367 157.085,96.367 157.085,96.181 156.056,96.181 156.056,95.994 157.085,95.994 157.085,95.807 156.056,95.807 156.056,95.621 157.085,95.621 157.085,95.434 156.423,95.434 156.423,95.247 157.085,95.247 157.085,95.237 157.014,95.166 155.082,93.235 155.082,90.174 155.157,90.1 155.157,89.798 155.036,89.677 155.036,88.324 v1(155.399,87.961)
DDR_CH1_DQS1_D_P: U3.D21 U12.W10 | length 28.4
  Top Layer 1 _Signal w0.161: U12.W10@154.804,104.789 155.155,104.439 v1(155.155,104.372) ; U3.D21@155.129,88.328 155.418,88.617 v1(155.443,88.617)
  Bottom Layer_Signals w0.161: v1(155.155,104.372) 155.2,104.327 155.2,104.136 155.275,104.061 155.275,100.725 156.202,99.799 156.202,99.497 156.145,99.44 156.145,99.306 156.514,98.938 156.514,98.12 157.398,97.236 157.398,95.107 157.153,94.863 157.096,94.806 157.143,94.758 156.994,94.608 156.946,94.656 156.796,94.506 157.489,93.813 157.339,93.663 156.646,94.356 156.497,94.206 157.189,93.513 157.039,93.363 156.347,94.056 156.197,93.906 156.889,93.213 156.739,93.063 156.047,93.756 155.897,93.606 156.589,92.913 156.439,92.763 155.747,93.456 155.597,93.306 156.289,92.613 156.14,92.463 155.546,93.056 155.396,92.906 155.396,92.526 155.396,90.304 155.47,90.23 155.47,89.668 155.35,89.548 155.35,88.711 v1(155.443,88.617)
DDR_CH1_LP4/4X_CKE0/LP5_CS0_C: R153.1 U3.D11 | length 21.6
  Top Layer 1 _Signal w0.203: U3.D11@148.629,88.328 148.638,88.328 148.93,88.036 v1(148.938,88.036)
  Bottom Layer_Signals w0.203: R153.1@148.214,98.517 148.217,98.517 R153.1@148.217,98.505 ; R153.1@148.214,98.532 148.21,98.532 148.198,98.521 148.198,98.33 148.1,98.33 148.1,98.101 148.254,98.101 148.254,97.873 148.1,97.873 148.1,97.644 148.455,97.644 148.455,97.416 148.279,97.416 148.279,97.187 148.286,97.187 148.286,97.085 148.286,96.549 148.213,96.476 147.783,96.046 147.601,96.046 147.601,95.825 147.947,95.825 147.947,95.604 147.554,95.604 147.554,95.383 147.947,95.383 147.947,95.162 147.554,95.162 147.554,94.941 147.947,94.941 147.947,94.72 147.554,94.72 147.554,94.499 147.947,94.499 147.947,94.278 147.554,94.278 147.554,94.057 147.947,94.057 147.947,93.836 147.554,93.836 147.554,93.615 147.947,93.615 147.947,93.394 147.554,93.394 147.554,93.173 147.947,93.173 147.947,92.952 147.554,92.952 147.554,92.63 147.554,91.926 147.899,91.582 148.132,91.348 148.058,91.274 148.22,91.112 148.329,91.222 148.491,91.06 148.381,90.951 148.543,90.789 148.879,91.125 149.04,90.963 148.705,90.627 148.866,90.466 148.941,90.54 149.014,90.467 149.014,90.203 149.014,90.118 149.014,90.007 149.392,90.007 149.392,89.779 149.014,89.779 149.014,89.55 149.361,89.55 149.361,89.322 148.927,89.322 148.927,89.093 148.938,89.093 148.938,88.991 148.938,88.929 148.68,88.671 148.68,88.469 148.682,88.467 148.682,88.345 148.938,88.089 v1(148.938,88.036)
DDR_CH1_LP4/4X_CKE0/LP5_CS0_D: R155.1 U3.D16 | length 20.9
  Top Layer 1 _Signal w0.203: v1(151.591,88.616) U3.D16@151.879,88.328
  Bottom Layer_Signals w0.203: R155.1@151.015,98.653 151.015,98.239 150.884,98.108 150.884,97.789 151.015,97.659 151.015,97.508 151.015,97.173 151.111,97.173 151.111,96.945 150.951,96.945 150.951,96.716 151.906,96.716 151.906,96.488 151.047,96.488 151.047,96.259 151.906,96.259 151.906,96.03 151.047,96.03 151.047,95.802 151.906,95.802 151.906,95.573 151.047,95.573 151.047,95.345 151.492,95.345 151.492,95.116 150.948,95.116 150.948,94.887 151.234,94.887 151.234,94.786 151.234,94.723 151.552,94.405 151.634,94.405 151.656,94.383 151.754,94.286 151.754,94.124 151.779,94.124 151.779,93.895 151.3,93.895 151.3,93.667 151.779,93.667 151.779,93.438 151.3,93.438 151.3,93.21 151.779,93.21 151.779,92.981 151.3,92.981 151.3,92.752 151.754,92.752 151.754,92.651 151.754,92.465 151.783,92.435 151.783,92.116 151.754,92.086 151.754,90.72 151.145,90.111 151.145,89.792 151.591,89.345 v1(151.591,88.616)
DDR_CH1_LP4/4X_CKE0_C: R153.2 U12.J4 | length 2
  Top Layer 1 _Signal w0.203: v1(147.941,100.391) 147.941,100.372 148.304,100.009 U12.J4@148.304,99.989
  Bottom Layer_Signals w0.203: v1(147.941,100.391) 147.941,100.338 148.21,100.069 148.21,99.895 148.32,99.785 148.32,99.466 148.309,99.455 148.309,99.229 148.235,99.155 R153.2@148.217,99.155
DDR_CH1_LP4/4X_CKE0_D: R155.2 U12.P4 | length 0.9
  Top Layer 1 _Signal w0.203: v1(151.25,99.687) 151.251,99.687 U12.P4@151.554,99.989
  Bottom Layer_Signals w0.203: R155.2@151.015,99.303 151.04,99.303 151.113,99.376 151.113,99.401 151.22,99.507 151.22,99.657 v1(151.25,99.687) v1@151.25,99.699
DDR_CH1_LP4/4X_CKE1/LP5_CS1_C: R154.1 U3.E11 | length 22.7
  Top Layer 1 _Signal w0.203: U3.E11@148.629,87.678 148.629,87.652 148.952,87.33 v1(148.954,87.33) v1@148.954,87.318
  Bottom Layer_Signals w0.203: R154.1@147.523,101.571 147.523,101.546 146.821,100.845 146.821,100.151 146.947,100.025 146.947,99.392 147.097,99.243 147.546,99.243 147.81,98.979 147.81,97.856 147.73,97.776 147.73,97.608 147.961,97.377 147.961,97.099 147.999,97.061 147.999,96.805 147.898,96.705 147.551,96.705 147.314,96.468 147.314,95.988 147.267,95.941 147.267,91.659 148.727,90.199 148.727,89.733 148.64,89.646 148.64,89.098 148.583,89.042 148.354,88.812 148.212,88.954 148.05,88.792 148.199,88.644 148.199,88.5 148.199,88.496 148.199,88.348 148.395,88.348 148.395,88.119 147.379,88.119 147.379,87.891 148.395,87.891 148.395,87.662 147.209,87.662 147.209,87.433 148.214,87.433 148.316,87.332 148.318,87.33 v1(148.954,87.33)
DDR_CH1_LP4/4X_CKE1/LP5_CS1_D: R156.1 U3.E16 | length 8.7
  Top Layer 1 _Signal w0.203: v1(151.573,87.986) 151.573,87.984 U3.E16@151.879,87.678
  Bottom Layer_Signals w0.203: R156.1@150.661,95.719 150.661,94.106 151.013,93.755 151.013,91.693 150.858,91.538 150.858,88.805 151.475,88.188 151.475,88.138 151.573,88.039 v1(151.573,87.986)
DDR_CH1_LP4/4X_CKE1_C: R154.2 U12.J5 | length 1.9
  Top Layer 1 _Signal w0.203: U12.J5@148.304,100.789 148.304,100.767 148.315,100.767 148.646,100.437 v1(148.646,100.426)
  Bottom Layer_Signals w0.203: R154.2@148.173,101.571 148.239,101.504 148.239,100.832 v1(148.646,100.426)
DDR_CH1_LP4/4X_CKE1_D: R156.2 U12.P5 | length 14.2
  Top Layer 1 _Signal w0.203: U12.P5@151.554,100.789 152.281,101.516 v1(152.346,101.516)
  Bottom Layer_Signals w0.203: R156.2@150.661,96.369 150.628,96.403 150.628,97.162 150.628,97.263 150.494,97.263 150.494,97.492 150.606,97.492 150.606,97.72 150.494,97.72 150.494,97.949 150.597,97.949 150.597,98.178 150.494,98.178 150.494,98.406 150.629,98.406 150.629,98.635 150.494,98.635 150.494,98.863 150.629,98.863 150.629,99.092 150.494,99.092 150.494,99.321 150.629,99.321 150.629,99.549 150.494,99.549 150.494,99.778 150.864,99.778 150.864,100.006 150.494,100.006 150.494,100.235 150.832,100.235 150.959,100.362 151.025,100.428 151.097,100.5 150.705,100.892 150.867,101.054 151.55,100.371 151.711,100.533 151.029,101.215 151.191,101.377 151.873,100.694 152.035,100.856 151.429,101.462 151.59,101.623 151.905,101.308 152.037,101.44 152.076,101.479 152.309,101.479 v1(152.346,101.516)
DDR_CH1_LP4/4X_CS0_C: U3.G11 U12.H4 | length 21.9
  Top Layer 1 _Signal w0.203: v1(147.352,99.637) 147.352,99.647 147.654,99.949 U12.H4@147.654,99.989 ; v1@148.304,86.76 v1(148.304,86.726) 148.304,86.703 U3.G11@148.629,86.378
  L3_Signals w0.179: v1(147.352,99.637) 147.76,99.228 147.76,98.702 147.485,98.427 147.308,98.427 147.032,98.151 147.032,97.427 147.068,97.392 147.068,97.082 147.032,97.047 147.032,97.028 147.032,96.639 147.066,96.605 146.721,96.26 146.865,96.115 147.499,96.749 147.644,96.605 147.01,95.971 147.155,95.826 147.789,96.46 147.934,96.315 147.3,95.681 147.444,95.536 147.789,95.881 147.916,95.755 147.98,95.691 148.045,95.626 148.045,95.081 148.045,94.991 148.22,94.991 148.22,94.786 147.807,94.786 147.807,94.582 148.22,94.582 148.22,94.377 147.807,94.377 147.807,94.172 148.203,94.172 148.203,93.968 148.045,93.968 148.045,91.746 148.045,91.144 148.715,90.475 148.715,89.09 148.302,88.677 148.302,86.744 148.294,86.736 v1(148.304,86.726)
DDR_CH1_LP4/4X_CS0_D: U3.E19 U12.R4 | length 18.2
  Top Layer 1 _Signal w0.203: U12.R4@152.204,99.989 152.204,100.028 152.503,100.327 v1(152.503,100.366)
  Top Layer 1 _Signal w0.205: v1(153.444,88.043) 153.454,88.043 153.819,87.678 U3.E19@153.829,87.678
  L3_Signals w0.179: v1(152.503,100.366) 152.842,100.027 153.721,100.027 153.743,100.027 153.795,99.974 153.848,100.027 153.993,99.882 153.689,99.578 153.834,99.434 154.154,99.753 154.298,99.609 153.979,99.289 154.123,99.144 154.443,99.464 154.588,99.319 154.54,99.272 154.685,99.127 154.715,99.156 154.79,99.081 154.854,99.017 154.875,98.996 154.875,98.287 154.769,98.182 154.769,98.098 153.877,97.205 153.877,95.635 153.929,95.583 153.929,95.274 153.877,95.222 153.877,90.831 153.154,90.108 153.154,89.798 153.372,89.579 153.512,89.579 153.735,89.356 153.735,89.183 153.846,89.072 153.846,88.444 v1(153.444,88.043)
DDR_CH1_LP4/4X_CS1_C: U3.H11 U12.H3 | length 21.7
  Top Layer 1 _Signal w0.205: v1(147.387,98.857) 147.387,98.889 147.654,99.157 U12.H3@147.654,99.189 ; v1@148.344,86.057 v1(148.344,86.038) 148.351,86.038 148.629,85.759 U3.H11@148.629,85.728
  L3_Signals w0.179: v1(147.387,98.857) 147.327,98.857 147.099,99.085 146.609,99.085 146.39,98.866 146.39,98.626 146.178,98.414 146.178,95.724 146.178,95.515 145.794,95.131 145.939,94.986 146.428,95.475 146.573,95.33 146.084,94.842 146.229,94.697 146.717,95.185 146.862,95.041 146.373,94.552 146.518,94.407 147.007,94.896 147.152,94.751 146.663,94.262 146.808,94.118 147.136,94.446 147.262,94.319 147.281,94.3 147.281,94.21 147.281,93.876 147.281,91.851 147.279,91.851 147.279,91.647 147.281,91.647 147.281,91.557 147.281,89.125 147.037,88.882 146.869,88.882 146.62,88.632 146.62,87.762 147.348,87.034 147.348,86.893 147.566,86.675 147.707,86.675 v1(148.344,86.038)
DDR_CH1_LP4/4X_CS1_D: U3.D19 U12.R3 | length 19.8
  Top Layer 1 _Signal w0.205: U12.R3@152.204,99.189 152.232,99.161 152.232,99.047 152.53,98.75 v1(152.53,98.717) ; v1(153.472,88.644) 153.513,88.644 U3.D19@153.829,88.328
  L3_Signals w0.179: v1(152.53,98.717) 152.589,98.717 152.885,98.421 153.958,98.421 154.185,98.194 154.185,97.885 153.776,97.476 153.068,97.476 152.659,97.067 152.659,95.661 153.601,94.719 153.601,94.49 153.601,94.253 153.614,94.253 153.614,94.048 152.921,94.048 152.921,93.844 153.614,93.844 153.614,93.639 152.921,93.639 152.921,93.434 153.614,93.434 153.614,93.229 152.921,93.229 152.921,93.025 153.614,93.025 153.614,92.82 153.071,92.82 153.071,92.615 153.601,92.615 153.601,92.525 153.601,91.105 153.154,90.657 153.154,90.48 152.89,90.217 152.89,89.689 153.263,89.316 153.403,89.316 153.472,89.247 v1(153.472,88.644)
DDR_RESET: U3.T4 U15.T11 | length 24.7
  Top Layer 1 _Signal w0.203: v1(127.67,85.267) 127.707,85.305 127.844,85.305 128.01,85.471 U15.T11@128.05,85.471 ; v1(143.814,80.299) 143.832,80.299 144.061,80.528 U3.T4@144.079,80.528
  Bottom Layer_Signals w0.203: v1(127.67,85.267) 127.659,85.257 127.659,83.293 127.635,83.269 127.635,82.949 127.659,82.925 127.659,82.672 128.485,81.847 128.494,81.847 129.083,81.258 129.083,80.836 128.792,80.544 128.792,79.784 129.308,79.267 130.834,79.267 130.837,79.265 131.116,79.265 131.119,79.267 131.81,79.267 132.221,78.857 132.54,78.857 132.806,79.122 132.974,79.122 133.096,79 133.664,79 133.931,79.267 136.975,79.267 137.07,79.363 137.175,79.363 137.44,79.628 138.804,79.628 138.923,79.747 138.923,79.801 139.149,80.027 139.556,80.027 139.628,80.099 140.911,80.099 140.978,80.166 141.297,80.166 141.364,80.099 141.566,80.099 141.933,80.466 141.933,80.855 142.301,81.222 142.62,81.222 142.871,80.971 142.871,80.323 142.99,80.204 143.208,80.204 143.303,80.299 v1(143.814,80.299)
DIODE: C587.1 Q17.1 Q17.3 U42.16 | length 8.6
  Top Layer 1 _Signal w0.457: U42.16@31.054,38.996 31.054,42.417 31.133,42.495 Q17.3@31.4,42.495 31.922,42.495 32.837,41.58 Q17.1@33.353,41.58 33.355,41.579 35.796,41.579 C587.1@35.797,41.578
DP0_AUXN: U3.AM15
DP0_AUXP: U3.AL15
DP0_MDC_DP: U47.42 U55.4 | length 255.7
  Top Layer 1 _Signal w0.254: v1(83.22,113.577) 83.12,113.577 83.166,113.53 U55.4@83.764,113.53 ; v1(211.492,97.043) 211.528,97.043 212.303,96.269 212.303,49.138 214.154,47.287 214.154,36.143 216.319,33.978 216.403,33.978 222.422,27.958 234.392,27.958 235.388,28.954 U47.42@235.388,32.634
  L8_Signals w0.254: v1(83.22,113.577) 81.942,113.577 81.587,113.932 78.761,113.932 78.406,113.577 74.189,113.577 74.162,113.549 73.951,113.549 73.802,113.698 73.802,117.511 78.354,122.063 78.834,122.063 78.849,122.047 83.675,122.047 84.395,122.767 90.14,122.767 91.015,121.892 94.478,121.892 98.012,118.359 159.97,118.359 160.053,118.442 190.093,118.442 v1(211.492,97.043)
DP0_MDC_RP: U35.12 U55.3 | length 64.4
  Top Layer 1 _Signal w0.254: U35.12@24.169,112.153 24.196,112.126 24.196,111.494 25.178,110.512 v1(27.367,110.512) ; v1(83.214,116.834) 83.242,116.806 83.242,116.502 83.764,115.98 U55.3@83.764,115.73
  L3_Signals w0.254: v1(27.367,110.512) 27.395,110.484 27.498,110.484 27.53,110.452 27.807,110.452 27.824,110.47 42.594,110.47 42.632,110.432 47.94,110.432 47.964,110.455 77.254,110.455 83.214,116.415 v1(83.214,116.834)
DP0_MDIO: IC1.2 U47.41 | length 242.5
  Top Layer 1 _Signal w0.254: IC1.2@70.202,122.018 70.858,122.018 71.113,122.273 v1(71.152,122.273) ; v1(212.778,97.658) 214.254,96.182 214.254,48.389 215.723,46.919 215.723,35.925 223.143,28.506 233.863,28.506 234.887,29.53 U47.41@234.887,32.634
  L8_Signals w0.254: v1(71.152,122.273) 71.19,122.273 71.304,122.387 71.91,122.387 72.896,123.372 94.32,123.372 98.643,119.05 190.301,119.05 203.717,105.634 204.802,105.634 v1(212.778,97.658)
DP0_TX2N: U3.AP15
DP0_TX2P: U3.AN15
DP0_TX3N: U3.AN16
DP0_TX3P: U3.AP16
DP1_MDC_DP: U49.42 U56.4 | length 229.4
  Top Layer 1 _Signal w0.254: U56.4@74.095,118.991 74.095,120.041 73.328,120.809 73.328,123.064 73.835,123.571 73.891,123.571 74.398,124.078 74.527,124.078 v1(74.555,124.106) ; v1(214.521,99.266) 217.143,96.644 217.143,47.409 219.563,44.989 225.575,44.989 230.991,50.405 U49.42@230.991,51.754
  L8_Signals w0.254: v1@74.509,124.06 76.278,125.829 98.001,125.829 103.48,120.35 193.793,120.35 202.88,111.263 202.88,111.197 214.509,99.568 214.509,99.278 v1(214.521,99.266)
DP1_MDC_RP: U35.13 U56.3 | length 55.4
  Top Layer 1 _Signal w0.254: U35.13@24.569,112.153 24.596,112.18 24.596,112.792 v1(25.212,113.408) ; v1(73.86,122.512) 73.86,122.472 74.095,122.237 U56.3@74.095,121.191
  L3_Signals w0.254: v1(25.212,113.408) 64.756,113.408 v1(73.86,122.512)
DP1_MDIO: IC1.3 U49.41 | length 229.1
  Top Layer 1 _Signal w0.254: IC1.3@70.202,122.418 70.229,122.445 70.666,122.445 70.949,122.728 v1(70.989,122.728) ; v1(215.056,100.452) 217.187,98.321 217.187,98.257 218.85,96.593 218.85,47.208 220.731,45.327 225.335,45.327 230.491,50.483 U49.41@230.491,51.754
  L8_Signals w0.254: v1(70.989,122.728) 70.989,122.744 76.082,127.838 97.595,127.838 104.231,121.201 194.306,121.201 v1(215.056,100.452)
DP_RST_DP0: U47.43 U57.4 | length 243.3
  Top Layer 1 _Signal w0.254: U57.4@74.358,113.599 74.358,114.438 74.491,114.572 v1(74.491,114.612) ; v1(210.088,96.478) 210.096,96.478 210.837,95.738 210.837,48.789 213.287,46.339 213.287,35.49 221.621,27.156 234.857,27.156 235.887,28.187 U47.43@235.887,32.634
  L8_Signals w0.254: v1(74.491,114.612) 74.491,114.621 74.999,115.128 75.069,115.128 81.651,121.709 89.312,121.709 90.4,120.622 93.569,120.622 96.301,117.89 188.676,117.89 v1(210.088,96.478)
DP_RST_DP1: U49.43 U58.4 | length 223.7
  Top Layer 1 _Signal w0.254: U58.4@78.594,118.739 78.594,120.02 78.183,120.431 78.183,121.753 80.226,123.795 80.496,123.795 v1(80.524,123.823) ; v1(213.857,98.454) 215.435,96.877 215.435,47.686 218.469,44.651 225.804,44.651 231.083,49.931 231.083,50.02 231.491,50.427 U49.43@231.491,51.754
  L8_Signals w0.254: v1(80.524,123.823) 81.524,124.823 96.814,124.823 101.928,119.709 192.622,119.709 203.464,108.867 203.464,108.701 213.683,98.482 213.829,98.482 v1(213.857,98.454)
EMMC.CLK: U1.D3 U4.P6 | length 22.1
  Top Layer 1 _Signal w0.132: v1(272.182,97.225) 272.205,97.225 272.649,97.669 U4.P6@272.672,97.669 ; v1(276.647,84.291) 277.217,83.721 277.217,82.517 277.261,82.473 277.261,82.409 277.466,82.204 277.466,80.845 276.981,80.36 U1.D3@276.981,80.08
  Bottom Layer_Signals w0.132: v1(272.182,97.225) 272.182,88.756 272.911,88.027 273.544,87.394 ccw(c273.637,87.487) 273.731,87.394 273.743,87.406 cw(c273.826,87.324) 273.908,87.406 cw(c273.826,87.324) 273.908,87.241 273.867,87.2 ccw(c273.95,87.118) 273.867,87.035 ccw(c273.95,87.118) 274.032,87.035 274.22,87.223 cw(c274.302,87.14) 274.385,87.223 cw(c274.302,87.14) 274.385,87.058 274.197,86.87 ccw(c274.28,86.788) 274.197,86.705 ccw(c274.28,86.788) 274.362,86.705 274.55,86.893 cw(c274.632,86.81) 274.715,86.893 cw(c274.632,86.81) 274.715,86.728 274.556,86.569 ccw(c274.649,86.475) 274.556,86.382 274.768,86.17 v1(276.647,84.291)
EMMC.CMD: U1.D2 U4.P5 | length 24.4
  Top Layer 1 _Signal w0.132: v1(272.345,99.036) 272.345,99.016 272.672,98.689 U4.P5@272.672,98.669 ; v1(276.761,81.289) 276.761,81.245 276.943,81.063 276.943,80.918 U1.D2@276.981,80.88
  L3_Signals w0.113: v1@272.346,99.036 273.028,98.354 273.028,92.036 273.028,91.98 273.053,91.98 273.053,91.829 272.8,91.829 272.8,91.679 273.053,91.679 273.053,91.528 272.8,91.528 272.8,91.378 273.053,91.378 273.053,91.227 272.8,91.227 272.8,91.076 273.053,91.076 273.053,90.926 272.8,90.926 272.8,90.775 273.053,90.775 273.053,90.624 272.8,90.624 272.8,90.474 273.053,90.474 273.053,90.323 272.8,90.323 272.8,90.173 273.053,90.173 273.053,90.022 272.8,90.022 272.8,89.871 273.053,89.871 273.053,89.721 272.911,89.721 272.911,89.57 273.028,89.57 273.028,89.299 273.028,85.022 v1(276.761,81.289)
EMMC.D0: U1.E1 U4.K2 | length 21.1
  Top Layer 1 _Signal w0.132: v1(276.095,87.369) 276.143,87.321 276.143,81.718 U1.E1@276.181,81.68 ; v1(276.264,101.217) 276.281,101.233 276.281,101.278 U4.K2@276.672,101.669
  Bottom Layer_Signals w0.132: v1(276.095,87.369) 276.095,90.293 276.095,90.516 cw(c276.227,90.516) 276.227,90.648 276.417,90.648 ccw(c276.417,90.726) 276.417,90.805 276.227,90.805 cw(c276.227,90.937) 276.095,90.937 276.095,92.62 276.095,97.846 275.865,98.076 275.865,100.818 v1(276.264,101.217)
EMMC.D1: U1.E2 U4.N2 | length 22.7
  Top Layer 1 _Signal w0.132: U4.N2@273.672,101.669 v1(274.106,101.234) ; v1(275.243,88.158) 275.696,87.705 275.696,81.55 275.658,81.512 275.658,81.403 U1.E2@276.181,80.88
  Bottom Layer_Signals w0.132: v1(274.106,101.234) 274.106,100.425 273.892,100.211 273.892,98.942 273.643,98.693 273.643,96.675 274.957,95.361 274.957,93.848 275.29,93.514 275.29,92.001 275.29,90.26 cw(c275.158,90.26) 275.158,90.128 275.057,90.128 ccw(c275.057,90.05) 275.057,89.971 275.158,89.971 cw(c275.158,89.839) 275.29,89.839 275.29,89.773 275.29,88.205 v1(275.243,88.158)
